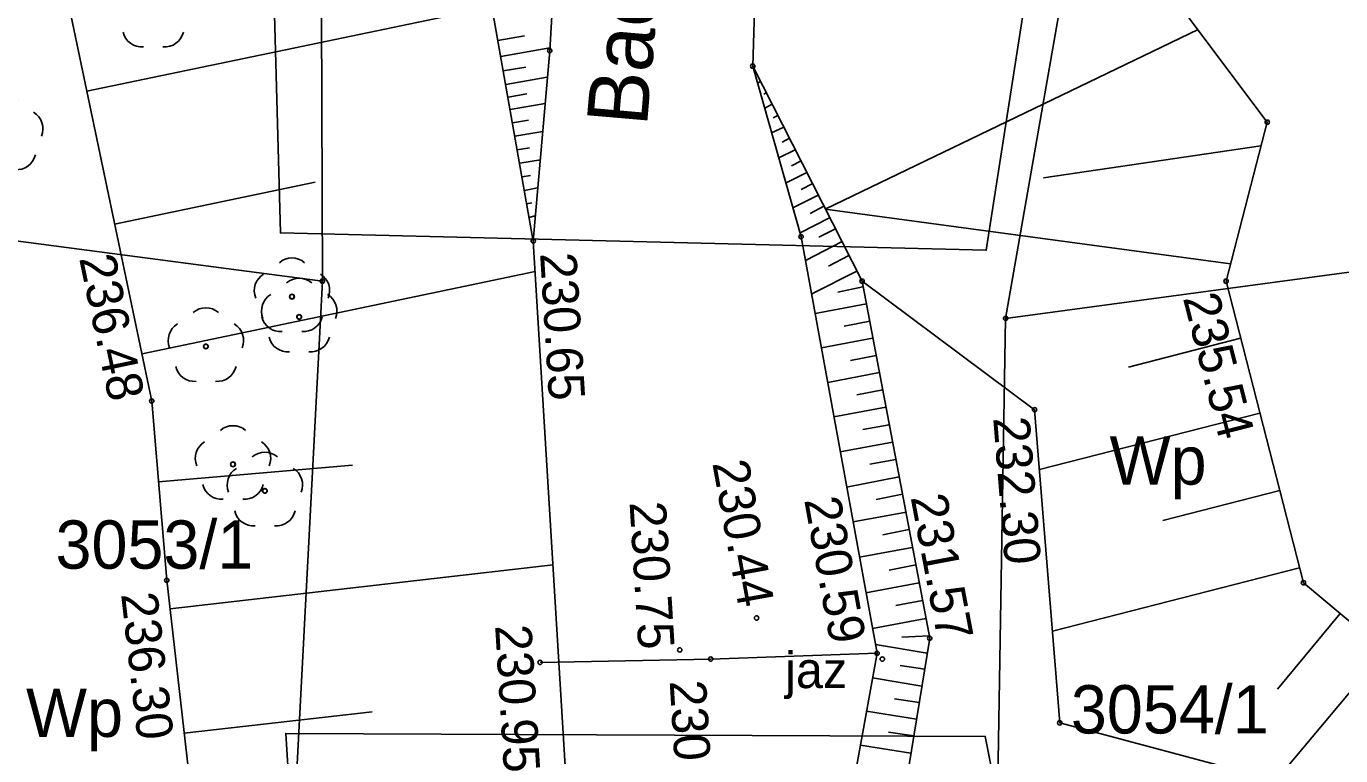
# Model space of a CAD drawing. Extents: x 6596400 to 6597200, y 5539751 to 5540251.
# Drawn here: x 6596725.66 to 6596752.84, y 5540064.18 to 5540079.28 of the extents above; entities that cross this region are included whole.
import ezdxf

# ---------------------------------------------------------------- set-up
doc = ezdxf.new("R2010")
doc.units = 0
for name, color, linetype in [('000 Inne (niezydentyfikowane)', 7, 'Continuous'), ('140-Punkty robocze', 7, 'Continuous'), ('203-punkt graniczny', 7, 'Continuous'), ('210-oznaczenie konturu użytku gruntowego', 7, 'Continuous'), ('211-numer działki ewidencyjnej', 7, 'Continuous'), ('218-kontur użytku gruntowego', 7, 'Continuous'), ('219-działka ewidencyjna', 7, 'Continuous'), ('drzewo liściaste', 7, 'Continuous'), ('jaz', 7, 'Continuous'), ('jaz-Atr17', 7, 'Continuous'), ('Linia obszaru zagospodarowania terenu', 7, 'Continuous'), ('pikieta sztuczna', 7, 'Continuous'), ('pikieta sztuczna-Atr2', 7, 'Continuous'), ('skarpa nieumocniona', 7, 'Continuous'), ('woda płynąca', 7, 'Continuous'), ('woda płynąca-Atr103', 7, 'Continuous')]:
    doc.layers.add(name, color=color, linetype=linetype)

# ---------------------------------------------------------------- blocks, each defined once
blk = doc.blocks.new('203')
blk.add_circle((0, 0), 0.045)
blk = doc.blocks.new('OP021')
blk.add_circle((0, 0), 0.05)
for centre, start, end in [((0, 0.4), 49.272, 130.728), ((-0.38, 0.124), 121.308, 202.548), ((0.38, 0.124), 337.452, 58.692), ((-0.235, -0.324), 193.221, 274.871), ((0.235, -0.324), 265.129, 346.779)]:
    blk.add_arc(centre, 0.4, start, end)
blk = doc.blocks.new('PIKIETA')
blk.add_circle((0, 0), 0.045)
blk = doc.blocks.new('PW01')
blk.add_circle((0, 0), 0.045)

msp = doc.modelspace()

# ---------------------------------------------------------------- linework, layer by layer
at = {"layer": '000 Inne (niezydentyfikowane)'}
for p, q in [((6596726.91, 5540077.93), (6596735.29, 5540079.68)), ((6596735.41, 5540078.98), (6596735.96, 5540079.08)), ((6596735.47, 5540078.65), (6596736.48, 5540078.83)), ((6596735.52, 5540078.35), (6596735.99, 5540078.43)), ((6596735.57, 5540078.07), (6596736.43, 5540078.22)), ((6596735.62, 5540077.81), (6596736.01, 5540077.88)), ((6596735.66, 5540077.55), (6596736.39, 5540077.68)), ((6596735.71, 5540077.28), (6596736.04, 5540077.33)), ((6596735.76, 5540077), (6596736.34, 5540077.1)), ((6596735.81, 5540076.72), (6596736.06, 5540076.76)), ((6596735.86, 5540076.44), (6596736.29, 5540076.51)), ((6596735.91, 5540076.16), (6596736.08, 5540076.19)), ((6596727.48, 5540075.18), (6596731.63, 5540076.05)), ((6596735.96, 5540075.88), (6596736.23, 5540075.93)), ((6596736, 5540075.6), (6596736.11, 5540075.62)), ((6596736.05, 5540075.32), (6596736.18, 5540075.35)), ((6596728.05, 5540072.5), (6596736.18, 5540074.2)), ((6596728.39, 5540069.85), (6596732.4, 5540070.19)), ((6596728.63, 5540067.22), (6596736.55, 5540068.13)), ((6596728.92, 5540064.65), (6596732.81, 5540065.09))]:
    msp.add_line(p, q, dxfattribs=at)
for points in [[(6596749.89, 5540079.21), (6596742.18, 5540075.49)], [(6596740.72, 5540078.37), (6596740.71, 5540078.36)], [(6596740.84, 5540078.13), (6596740.78, 5540078.1)], [(6596740.96, 5540077.9), (6596740.91, 5540077.87)], [(6596741.08, 5540077.66), (6596740.93, 5540077.58)], [(6596741.2, 5540077.43), (6596741.1, 5540077.38)], [(6596741.32, 5540077.19), (6596741.07, 5540077.07)], [(6596741.44, 5540076.96), (6596741.29, 5540076.88)], [(6596741.56, 5540076.72), (6596741.22, 5540076.55)], [(6596751.19, 5540076.8), (6596746.69, 5540076.14)], [(6596741.68, 5540076.49), (6596741.48, 5540076.39)], [(6596741.8, 5540076.25), (6596741.36, 5540076.03)], [(6596741.92, 5540076.02), (6596741.68, 5540075.9)], [(6596742.03, 5540075.78), (6596741.51, 5540075.52)], [(6596742.15, 5540075.55), (6596741.87, 5540075.4)], [(6596750.56, 5540074.36), (6596742.18, 5540075.49)], [(6596742.27, 5540075.31), (6596741.66, 5540075)], [(6596742.39, 5540075.08), (6596742.05, 5540074.91)], [(6596742.53, 5540074.82), (6596741.77, 5540074.43)], [(6596742.67, 5540074.53), (6596742.25, 5540074.31)], [(6596742.83, 5540074.21), (6596741.9, 5540073.74)], [(6596742.96, 5540073.88), (6596742.44, 5540073.77)], [(6596743.03, 5540073.53), (6596741.97, 5540073.33)], [(6596743.1, 5540073.17), (6596742.57, 5540073.07)], [(6596743.16, 5540072.82), (6596742.1, 5540072.62)], [(6596750.77, 5540072.82), (6596748.45, 5540072.22)], [(6596743.23, 5540072.46), (6596742.7, 5540072.36)], [(6596743.3, 5540072.11), (6596742.23, 5540071.9)], [(6596743.37, 5540071.75), (6596742.83, 5540071.65)], [(6596743.43, 5540071.39), (6596742.36, 5540071.19)], [(6596751.17, 5540071.27), (6596746.61, 5540070.1)], [(6596743.5, 5540071.03), (6596742.96, 5540070.93)], [(6596743.57, 5540070.67), (6596742.49, 5540070.47)], [(6596743.64, 5540070.31), (6596743.1, 5540070.21)], [(6596743.71, 5540069.95), (6596742.62, 5540069.74)], [(6596751.58, 5540069.67), (6596749.16, 5540069.05)], [(6596743.78, 5540069.59), (6596743.23, 5540069.48)], [(6596743.85, 5540069.22), (6596742.76, 5540069.02)], [(6596743.91, 5540068.86), (6596743.37, 5540068.75)], [(6596743.98, 5540068.49), (6596742.89, 5540068.29)], [(6596744.05, 5540068.13), (6596743.5, 5540068.02)], [(6596751.99, 5540068.07), (6596746.88, 5540066.76)], [(6596744.12, 5540067.76), (6596743.02, 5540067.55)], [(6596744.19, 5540067.39), (6596743.64, 5540067.29)], [(6596744.26, 5540067.02), (6596743.16, 5540066.81)], [(6596752.83, 5540067.12), (6596751.53, 5540065.56)], [(6596744.33, 5540066.66), (6596743.76, 5540066.63)], [(6596744.29, 5540066.3), (6596743.22, 5540066.48)], [(6596753.75, 5540066.36), (6596751.5, 5540063.67)], [(6596744.24, 5540065.97), (6596743.73, 5540066.05)], [(6596744.18, 5540065.62), (6596743.16, 5540065.79)], [(6596744.12, 5540065.28), (6596743.61, 5540065.36)], [(6596744.07, 5540064.94), (6596743.03, 5540065.1)], [(6596744.01, 5540064.59), (6596743.49, 5540064.67)], [(6596743.95, 5540064.23), (6596742.91, 5540064.4)]]:
    msp.add_lwpolyline(points, dxfattribs=at)
at = {"layer": '218-kontur użytku gruntowego'}
for points in [[(6596745.91, 5540073.23), (6596750.12, 5540097.31)], [(6596750.12, 5540097.31), (6596745.91, 5540073.23)], [(6596731.7, 5540096.09), (6596731.78, 5540074)], [(6596731.78, 5540074), (6596731.7, 5540096.09)], [(6596725.18, 5540074.87), (6596731.78, 5540074)], [(6596731.78, 5540074), (6596725.18, 5540074.87)], [(6596731.78, 5540074), (6596731.23, 5540063.48)], [(6596731.23, 5540063.48), (6596731.78, 5540074)], [(6596745.91, 5540073.23), (6596753.12, 5540074.2)], [(6596753.12, 5540074.2), (6596745.91, 5540073.23)], [(6596745.74, 5540063.25), (6596745.91, 5540073.23)], [(6596745.91, 5540073.23), (6596745.74, 5540063.25)]]:
    msp.add_lwpolyline(points, dxfattribs=at)
at = {"layer": '219-działka ewidencyjna'}
for points in [[(6596745.91, 5540073.23), (6596750.12, 5540097.31)], [(6596731.78, 5540074), (6596731.7, 5540096.09)], [(6596731.78, 5540074), (6596725.18, 5540074.87)], [(6596731.23, 5540063.48), (6596731.78, 5540074)], [(6596745.91, 5540073.23), (6596753.12, 5540074.2)], [(6596745.74, 5540063.25), (6596745.91, 5540073.23)]]:
    msp.add_lwpolyline(points, dxfattribs=at)
at = {"layer": 'jaz'}
msp.add_lwpolyline([(6596736.28, 5540066.11), (6596739.81, 5540066.18), (6596743.25, 5540066.3)], dxfattribs=at)
at = {"layer": 'Linia obszaru zagospodarowania terenu'}
for points in [[(6596664.616, 5540132.112), (6596671.21, 5540127.95), (6596681.8, 5540121.54), (6596690.35, 5540115.69), (6596701.61, 5540105.97), (6596709.34, 5540098.61), (6596715.39, 5540091.82), (6596718.63, 5540088.53), (6596721.87, 5540084.71), (6596726.1, 5540083.21), (6596730.7, 5540082.79), (6596730.91, 5540075), (6596745.51, 5540074.64), (6596746.77, 5540082.74), (6596765.15, 5540085.09), (6596776.62, 5540086.27), (6596789.34, 5540086.1), (6596798.37, 5540085.54), (6596805.65, 5540083.56), (6596813.11, 5540081.53), (6596819.41, 5540077.54), (6596826.58, 5540072.81), (6596832.721, 5540067.998)], [(6596720.263, 5540058.387), (6596728.96, 5540057.84), (6596731.45, 5540057.76), (6596731.02, 5540064.64), (6596745.49, 5540064.58), (6596746.99, 5540056.99), (6596772.84, 5540062.25), (6596786.21, 5540064.83), (6596807.99, 5540057.58), (6596818.837, 5540049.192)]]:
    msp.add_lwpolyline(points, dxfattribs=at)
at = {"layer": 'skarpa nieumocniona'}
for points in [[(6596733.94, 5540086.32), (6596732.43, 5540082.43), (6596735.19, 5540080.23), (6596736.14, 5540074.83), (6596737.01, 5540060.57), (6596734.88, 5540056.12), (6596737.49, 5540048.7), (6596742.37, 5540041.71), (6596738.78, 5540039.69), (6596738.22, 5540031.96), (6596734.92, 5540032.83), (6596735.24, 5540039.91), (6596732.47, 5540046.87), (6596731.97, 5540049.93), (6596729.74, 5540057.45), (6596728.56, 5540067.81), (6596728.25, 5540071.52), (6596725.74, 5540083.5), (6596726.85, 5540087.53)], [(6596733.94, 5540086.32), (6596732.43, 5540082.43), (6596735.19, 5540080.23), (6596736.14, 5540074.83), (6596737.01, 5540060.57), (6596734.88, 5540056.12), (6596737.49, 5540048.7), (6596742.37, 5540041.71), (6596738.78, 5540039.69), (6596738.22, 5540031.96), (6596734.92, 5540032.83), (6596735.24, 5540039.91), (6596732.47, 5540046.87), (6596731.97, 5540049.93), (6596729.74, 5540057.45), (6596728.56, 5540067.81), (6596728.25, 5540071.52), (6596725.74, 5540083.5), (6596726.85, 5540087.53)], [(6596756.22, 5540066.9), (6596754.09, 5540066.07), (6596752.07, 5540067.76), (6596750.47, 5540074), (6596751.32, 5540077.29), (6596748.52, 5540081.03), (6596740.72, 5540079.85), (6596740.68, 5540078.45), (6596742.94, 5540074), (6596746.51, 5540071.34), (6596747.03, 5540064.86), (6596756.25, 5540062.4), (6596756.95, 5540064.41)], [(6596756.22, 5540066.9), (6596754.09, 5540066.07), (6596752.07, 5540067.76), (6596750.47, 5540074), (6596751.32, 5540077.29), (6596748.52, 5540081.03), (6596740.72, 5540079.85), (6596740.68, 5540078.45), (6596742.94, 5540074), (6596746.51, 5540071.34), (6596747.03, 5540064.86), (6596756.25, 5540062.4), (6596756.95, 5540064.41)], [(6596756.16, 5540061.25), (6596751.77, 5540058.62), (6596746.79, 5540058.12), (6596745.06, 5540060.97), (6596743.75, 5540062.98), (6596744.34, 5540066.61), (6596742.94, 5540074), (6596740.68, 5540078.45), (6596741.68, 5540074.92), (6596743.25, 5540066.3), (6596742.47, 5540061.97), (6596741.65, 5540054.82), (6596746.75, 5540055.19), (6596752.07, 5540056.28), (6596754.58, 5540058.6), (6596758.63, 5540061.34)], [(6596756.16, 5540061.25), (6596751.77, 5540058.62), (6596746.79, 5540058.12), (6596745.06, 5540060.97), (6596743.75, 5540062.98), (6596744.34, 5540066.61), (6596742.94, 5540074), (6596740.68, 5540078.45), (6596741.68, 5540074.92), (6596743.25, 5540066.3), (6596742.47, 5540061.97), (6596741.65, 5540054.82), (6596746.75, 5540055.19), (6596752.07, 5540056.28), (6596754.58, 5540058.6), (6596758.63, 5540061.34)]]:
    msp.add_lwpolyline(points, close=True, dxfattribs=at)
msp.add_lwpolyline([(6596736.56, 5540080.1), (6596736.48, 5540078.77), (6596736.14, 5540074.83), (6596735.19, 5540080.23)], dxfattribs=at)
msp.add_lwpolyline([(6596736.56, 5540080.1), (6596736.48, 5540078.77), (6596736.14, 5540074.83), (6596735.19, 5540080.23)], dxfattribs=at)
at = {"layer": 'woda płynąca'}
for points in [[(6596746.88, 5540042.02), (6596743.2, 5540046.89), (6596742.01, 5540050.53), (6596741.65, 5540054.82), (6596742.47, 5540061.97), (6596743.25, 5540066.3), (6596741.68, 5540074.92), (6596740.68, 5540078.45), (6596740.72, 5540079.85), (6596740.91, 5540084.82), (6596741.25, 5540084.94), (6596740.92, 5540088.42), (6596742.42, 5540096.36), (6596743.6, 5540103.66), (6596744.49, 5540107.55), (6596747.66, 5540110.25), (6596750.9, 5540111.08), (6596759.95, 5540110.31), (6596765.11, 5540108.34), (6596769.44, 5540104.84), (6596775.99, 5540100.07), (6596783.39, 5540096.06), (6596790.43, 5540094.51)], [(6596736.53, 5540085.88), (6596736.56, 5540080.1), (6596736.48, 5540078.77), (6596736.14, 5540074.83), (6596737.01, 5540060.57), (6596737.04, 5540056.69), (6596739.69, 5540049.9), (6596742.87, 5540042.02), (6596744.95, 5540040.49), (6596747.16, 5540032.77), (6596747.69, 5540030.285)]]:
    msp.add_lwpolyline(points, dxfattribs=at)

# ---------------------------------------------------------------- block references
at = {"layer": '140-Punkty robocze'}
for p in [(6596736.48, 5540078.77), (6596740.68, 5540078.45), (6596751.32, 5540077.29), (6596736.14, 5540074.83), (6596741.68, 5540074.92), (6596742.94, 5540074), (6596750.47, 5540074), (6596731.15, 5540073.68), (6596731.3, 5540073.26), (6596729.37, 5540072.65), (6596728.25, 5540071.52), (6596746.51, 5540071.34), (6596729.93, 5540070.21), (6596730.59, 5540069.66), (6596728.56, 5540067.81), (6596752.07, 5540067.76), (6596740.76, 5540067.03), (6596744.34, 5540066.61), (6596739.17, 5540066.37), (6596743.25, 5540066.3), (6596736.28, 5540066.11), (6596739.81, 5540066.18), (6596743.36, 5540066.18), (6596747.03, 5540064.86)]:
    msp.add_blockref('PIKIETA', p, dxfattribs=at)
at = {"layer": '203-punkt graniczny'}
for p in [(6596731.78, 5540074), (6596745.91, 5540073.23)]:
    msp.add_blockref('203', p, dxfattribs=at)
at = {"layer": 'drzewo liściaste'}
for p in [(6596728.28, 5540079.57), (6596725.22, 5540077.03), (6596731.15, 5540073.68), (6596731.3, 5540073.26), (6596729.37, 5540072.65), (6596729.93, 5540070.21), (6596730.59, 5540069.66)]:
    msp.add_blockref('OP021', p, dxfattribs=at)
at = {"layer": 'pikieta sztuczna'}
for p in [(6596736.14, 5540074.83), (6596750.47, 5540074), (6596728.25, 5540071.52), (6596746.51, 5540071.34), (6596728.56, 5540067.81), (6596740.76, 5540067.03), (6596744.34, 5540066.61), (6596739.17, 5540066.37), (6596743.25, 5540066.3), (6596736.28, 5540066.11), (6596739.81, 5540066.18)]:
    msp.add_blockref('PW01', p, dxfattribs=at)

# ---------------------------------------------------------------- texts
at = {"layer": '210-oznaczenie konturu użytku gruntowego'}
for p in [(6596748.06, 5540069.79), (6596725.65, 5540064.57)]:
    msp.add_text('Wp', height=1, dxfattribs=at).set_placement(p)
at = {"layer": '211-numer działki ewidencyjnej'}
for s, p in [('3053/1', (6596726.26, 5540068.05)), ('3054/1', (6596747.26, 5540064.64))]:
    msp.add_text(s, height=1, dxfattribs=at).set_placement(p)
at = {"layer": 'jaz-Atr17'}
msp.add_text('jaz', height=0.75, dxfattribs=at).set_placement((6596741.35, 5540065.58))
at = {"layer": 'pikieta sztuczna-Atr2'}
for s, rotation, p in [('236.48', 281.833, (6596726.746, 5540074.476)), ('230.65', 273.491, (6596736.281, 5540074.574)), ('235.54', 284.381, (6596749.574, 5540073.654)), ('232.30', 274.588, (6596745.652, 5540071.17)), ('230.44', 280.322, (6596739.842, 5540070.236)), ('230.75', 273.491, (6596738.131, 5540069.424)), ('230.59', 280.322, (6596741.742, 5540069.476)), ('231.57', 280.727, (6596743.943, 5540069.53)), ('236.30', 276.498, (6596727.615, 5540067.525)), ('230.95', 273.491, (6596735.351, 5540066.874)), ('230.86', 273.491, (6596738.961, 5540065.724))]:
    msp.add_text(s, height=0.75, rotation=rotation, dxfattribs=at).set_placement(p)
at = {"layer": 'woda płynąca-Atr103'}
msp.add_text('Bachorz', height=1.25, rotation=85.068, dxfattribs=at).set_placement((6596738.49, 5540077.19))
msp.add_text('Bachorz', height=1.25, rotation=85.068, dxfattribs=at).set_placement((6596738.49, 5540077.19))
msp.add_text('Bachorz', height=1.25, rotation=85.068, dxfattribs=at).set_placement((6596738.49, 5540077.19))

doc.saveas('drawing.dxf')
